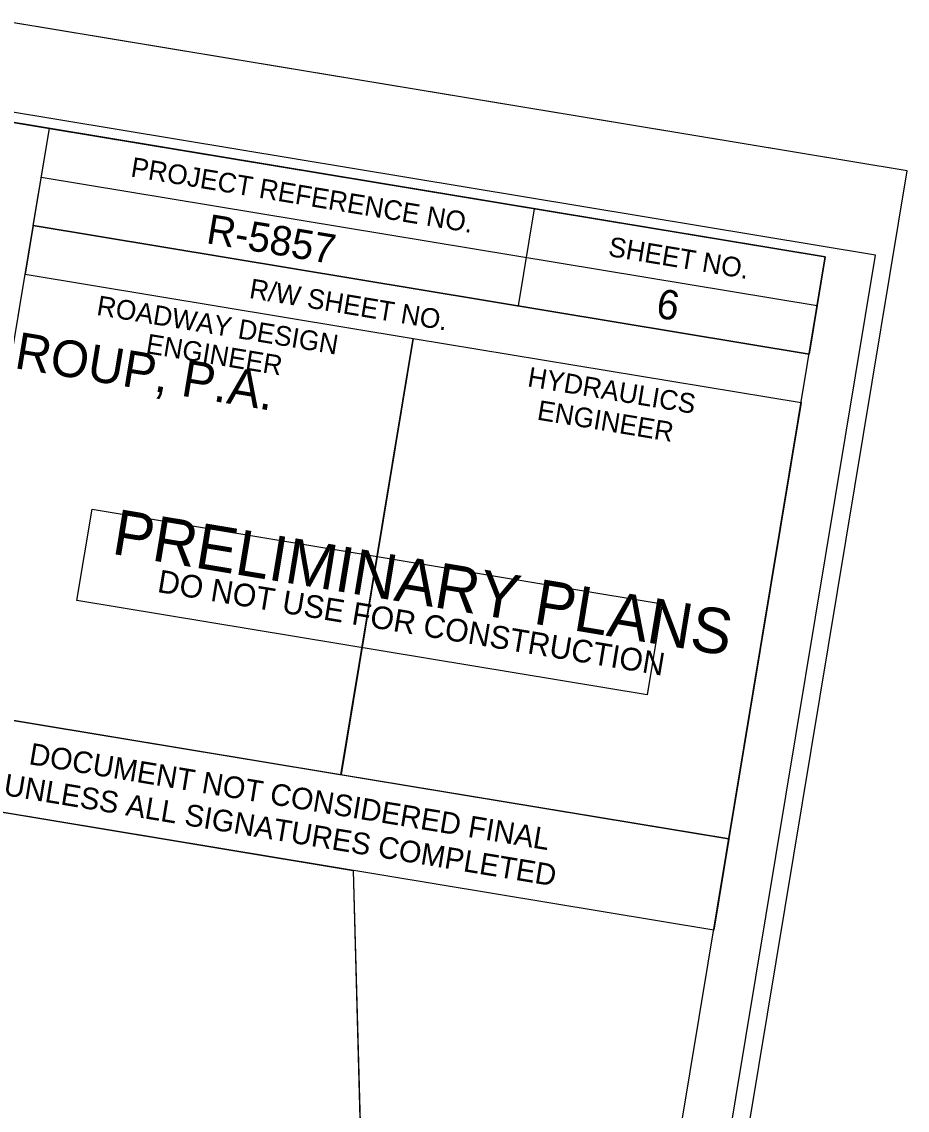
# Model space of a CAD drawing. Extents: x 2191522 to 2193565, y 85992 to 87403.
# Drawn here: x 2193138.2 to 2193363.4, y 86838.6 to 87115.4 of the extents above; entities that cross this region are included whole.
import ezdxf

# ---------------------------------------------------------------- set-up
doc = ezdxf.new("R2010")
doc.units = 0
for name, color, linetype in [('Exist Structure Minor Footbridge Terminator', 7, 'Continuous'), ('Old_Level_11', 7, 'Continuous'), ('Old_Level_2', 7, 'Continuous'), ('Scratch_Level_0', 7, 'Continuous'), ('Sheet Border Standard 30in CELL', 7, 'Continuous'), ('Sheet Cutting Line CELL', 7, 'Continuous'), ('Sheet Data Field CELL', 7, 'Continuous'), ('Sheet Plot Border Inside CELL', 7, 'Continuous'), ('Sheet Plot Border Outside CELL', 7, 'Continuous'), ('Sheet Sticker Exception Certification CELL', 7, 'Continuous')]:
    doc.layers.add(name, color=color, linetype=linetype)

msp = doc.modelspace()

# ---------------------------------------------------------------- linework, layer by layer
at = {"layer": 'Exist Structure Minor Footbridge Terminator'}
msp.add_lwpolyline([(2193152.22, 86968.27), (2193156.06, 86991.46), (2193301.08, 86967.43), (2193297.24, 86944.24)], close=True, dxfattribs=at)
at = {"layer": 'Old_Level_11'}
for p in [(2193012.61, 87110.3), (2193137.28, 87040.56)]:
    msp.add_line(p, (2193145.2, 87088.33), dxfattribs=at)
at = {"layer": 'Old_Level_2'}
msp.add_lwpolyline([(2192433.98, 86441.81), (2191739.47, 86556.89), (2191853.01, 87242.11), (2191862.74, 87300.84), (2193012.61, 87110.3), (2193009.43, 87091.1), (2192997.5, 87019.11), (2193130.09, 86997.14), (2193116.83, 86917.12), (2193222.5, 86899.61), (2193235.64, 86410.38), (2193213.75, 86278.09), (2193023.91, 86309.51), (2192994.12, 86129.44), (2192901.35, 86144.8), (2192889.18, 86066.44), (2192560.71, 86120.87), (2192457.88, 86381.28)], close=True, dxfattribs=at)
at = {"layer": 'Scratch_Level_0'}
msp.add_line((2193222.5, 86899.61), (2193235.64, 86410.38), dxfattribs=at)
at = {"layer": 'Sheet Border Standard 30in CELL'}
for p, q in [((2193143.15, 87075.95), (2193340.51, 87043.25)), ((2193268.56, 87067.84), (2193264.47, 87043.18)), ((2193141.11, 87063.62), (2193139.06, 87051.29)), ((2193141.11, 87063.62), (2193338.47, 87030.92)), ((2193141.11, 87063.62), (2193338.47, 87030.92)), ((2193237.77, 87034.93), (2193219.39, 86924))]:
    msp.add_line(p, q, dxfattribs=at)
for points in [[(2193342.56, 87055.63), (2191862.74, 87300.84), (2191691.1, 86264.96), (2193170.92, 86019.76)], [(2193145.2, 87088.33), (2193342.56, 87055.63), (2193338.47, 87030.92), (2193141.11, 87063.62)], [(2193139.06, 87051.29), (2193237.77, 87034.93), (2193219.38, 86923.95), (2193120.67, 86940.3)], [(2193237.77, 87034.93), (2193336.42, 87018.59), (2193318.03, 86907.6), (2193219.38, 86923.95)]]:
    msp.add_lwpolyline(points, close=True, dxfattribs=at)
at = {"layer": 'Sheet Cutting Line CELL'}
msp.add_line((2193363.42, 87077.52), (2191702.07, 87352.8), dxfattribs=at)
at = {"layer": 'Sheet Plot Border Inside CELL'}
msp.add_lwpolyline([(2193355.31, 87056.1), (2191711.23, 87328.53), (2191538.75, 86287.62), (2193182.83, 86015.2)], close=True, dxfattribs=at)
at = {"layer": 'Sheet Plot Border Outside CELL'}
msp.add_lwpolyline([(2193363.42, 87077.52), (2191702.07, 87352.8), (2191522.25, 86267.6), (2193183.6, 85992.31)], close=True, dxfattribs=at)
at = {"layer": 'Sheet Sticker Exception Certification CELL'}
for p, q in [((2193120.67, 86940.3), (2193318.02, 86907.6)), ((2193314.18, 86884.42), (2193116.83, 86917.12)), ((2193318.02, 86907.59), (2193314.18, 86884.41))]:
    msp.add_line(p, q, dxfattribs=at)

# ---------------------------------------------------------------- texts
at = {"layer": 'Exist Structure Minor Footbridge Terminator'}
for s, height, p in [('PRELIMINARY PLANS', 11.52, (2193160.78, 86980.18)), ('DO NOT USE FOR CONSTRUCTION', 5.76, (2193172.45, 86970.44))]:
    msp.add_text(s, height=height, rotation=350.5917, dxfattribs=at).set_placement(p)
at = {"layer": 'Sheet Border Standard 30in CELL'}
for s, height, p in [('PROJECT REFERENCE NO.', 5.0001, (2193165.68, 87076.12)), ('SHEET NO.', 5, (2193287.16, 87055.89)), ('SUNGATE DESIGN GROUP, P.A.', 9.3194, (2193013.09, 87047.77)), ('R/W SHEET NO.', 5.0001, (2193195.84, 87045.23)), ('ROADWAY DESIGN', 5.0001, (2193157.01, 87040.92)), ('ENGINEER', 5, (2193169.54, 87031.19)), ('HYDRAULICS', 5, (2193266.61, 87022.75)), ('ENGINEER', 5, (2193269.06, 87014.29))]:
    msp.add_text(s, height=height, rotation=350.5917, dxfattribs=at).set_placement(p)
at = {"layer": 'Sheet Data Field CELL'}
for s, p in [('R-5857', (2193184.86, 87059.16)), ('6', (2193299.25, 87040.26))]:
    msp.add_text(s, height=7.5, rotation=350.5917, dxfattribs=at).set_placement(p)
at = {"layer": 'Sheet Sticker Exception Certification CELL'}
for s, p in [('DOCUMENT NOT CONSIDERED FINAL', (2193139.77, 86926.65)), ('UNLESS ALL SIGNATURES COMPLETED', (2193133.33, 86918.8))]:
    msp.add_text(s, height=5.5, rotation=350.5917, dxfattribs=at).set_placement(p)

doc.saveas('drawing.dxf')
